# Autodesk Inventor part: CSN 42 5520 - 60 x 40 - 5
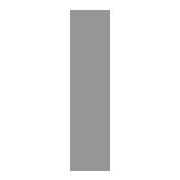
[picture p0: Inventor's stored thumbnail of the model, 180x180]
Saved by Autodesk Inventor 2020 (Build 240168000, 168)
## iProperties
Created: 2019-01
Part Number: CSN 42 5520 - 60 x 40 - 5
Material: Ocel, měkká
Description: Tyč
Document SubType Name: Modeling
Standard: CSN 42 5520
Designer: doma
Standards Organization: CSN
Language: cs-CZ
Size Designation: 60 x 40 - 5
Categories: <MemberInstance><Categories><Category DisplayName="Konstrukční profily" InternalName="089c4875-fa83-4c05-b084-43b9cc11f5ed" Mnemonic="GRDR"><CategoryParameter D
Stock Number: 60 x 40
Density: 7.85 g/cm^3
Appearance: Pololeštěná
Mass: 90.8308 g
Surface Area: 55.4248 cm^2
Volume: 11.5708 cm^3
IsCustomPart: 1
G_L: 5,000 mm
Author: doma
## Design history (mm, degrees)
node "Počáteční rovina"
node "Koncová rovina"
sketch "Náčrt"
  geometry: L1 (20, -30)-(-20, -30); L2 (-20, -30)-(-20, 30); L3 (-20, 30)-(20, 30); L4 (20, 30)-(20, -30); L5 (-6, 0)-(8, 0); L6 (0, -30)-(0, 40); L7 (0, 54)-(0, -44) reference; L8 (-9.2, 0)-(13.2, 0) reference
  constraints: 12 end point, 2 collinear, 2 parallel, 1 horizontal, 1 perpendicular
  dimensions: "d0" = 60 distance between parallel lines of L3 L1 (= G_W); "d1" = 40 distance between parallel lines of L4 L2 (= G_H); "d4" = 20 distance between parallel lines of L6 L4 (= 0.5 x d1); "d5" = 30 distance between parallel lines of L5 L3 (= 0.5 x d0)
extrude "Těleso" new body sketch "Náčrt" stored distance "d2" = 5 (= G_L); taper "d3" = 0 deg
node "Driven Length"
  sketch "Sketch3"
    geometry: L1 (0, 0)-(10, 0) reference
    constraints: 2 end point, 1 horizontal
  workplane "Work Plane3"
  sketch "Sketch4"
    geometry: L1 (-2, 0)-(12, 0) reference; L2 (-2, 5)-(12, 5) reference
    dimensions: "d9" = 5 distance between parallel lines of L1 L2 (derived)
sketch "Náčrt5"
  geometry: L1 (-10, 30)-(10, 30); L2 (20, 30)-(-20, 30) reference; L3 (20, 20)-(20, -20); L4 (20, -30)-(20, 30) reference; L5 (-10, -30)-(10, -30); L6 (-20, -30)-(20, -30) reference; L7 (-20, -20)-(-20, 20); L8 (-20, 30)-(-20, -30) reference; A1 r 10 centre (10, 20) between (20, 20) and (10, 30) reference; A2 r 10 centre (-10, 20) between (-10, 30) and (-20, 20) reference; A3 r 10 centre (-10, -20) between (-20, -20) and (-10, -30) reference; A4 r 10 centre (10, -20) between (10, -30) and (20, -20) reference; 1 further point
  constraints: 8 end point, 4 collinear, 3 tangent
extrude "Vysunutí2" cut sketch "Náčrt5" distance "d10" = 10; taper "d11" = 0 deg
sketch "Náčrt6"
  geometry: 2 further points
  constraints: 1 coincident
hole "Díra1" sketch "Náčrt6" at (0, 0) diameter "d12" = 13.835; stored, may be unused: countersink angle "d16" = 90 deg, drill point angle "d18" = 118 deg; dims "d13" = 32, "d14" = 4, "d15" = 2, "d17" = 41.3
body "Solid1"
node "Referenční1"
node "Referenční2"
node "Referenční3"
node "Referenční4"
other parameters: "G_W" = 60 [user parameter; used in 1 equation term], "G_H" = 40 [user parameter; used in 1 equation term], "G_L" = 5 (= d9) [user parameter; used in 1 equation term], "G_OFFSET_START" = 0 [user parameter; used in 1 equation term], "G_OFFSET_END" = 0 [user parameter; used in 1 equation term], "d6" = 0 (computed from G_OFFSET_START), "d7" = 5 (= G_OFFSET_END + B_L), "B_L" = 5 [user parameter; used in 1 equation term], "d8" = 90 deg
